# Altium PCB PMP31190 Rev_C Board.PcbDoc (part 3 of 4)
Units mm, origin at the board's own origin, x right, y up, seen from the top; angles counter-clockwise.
Board outline 175.26 x 91.44 mm, 4 copper layers (Top Layer, Mid-Layer 1, Mid-Layer 2, Bottom Layer), stack 1.473 mm thick; 252 components, 140 nets, 735 pads, 501 vias.
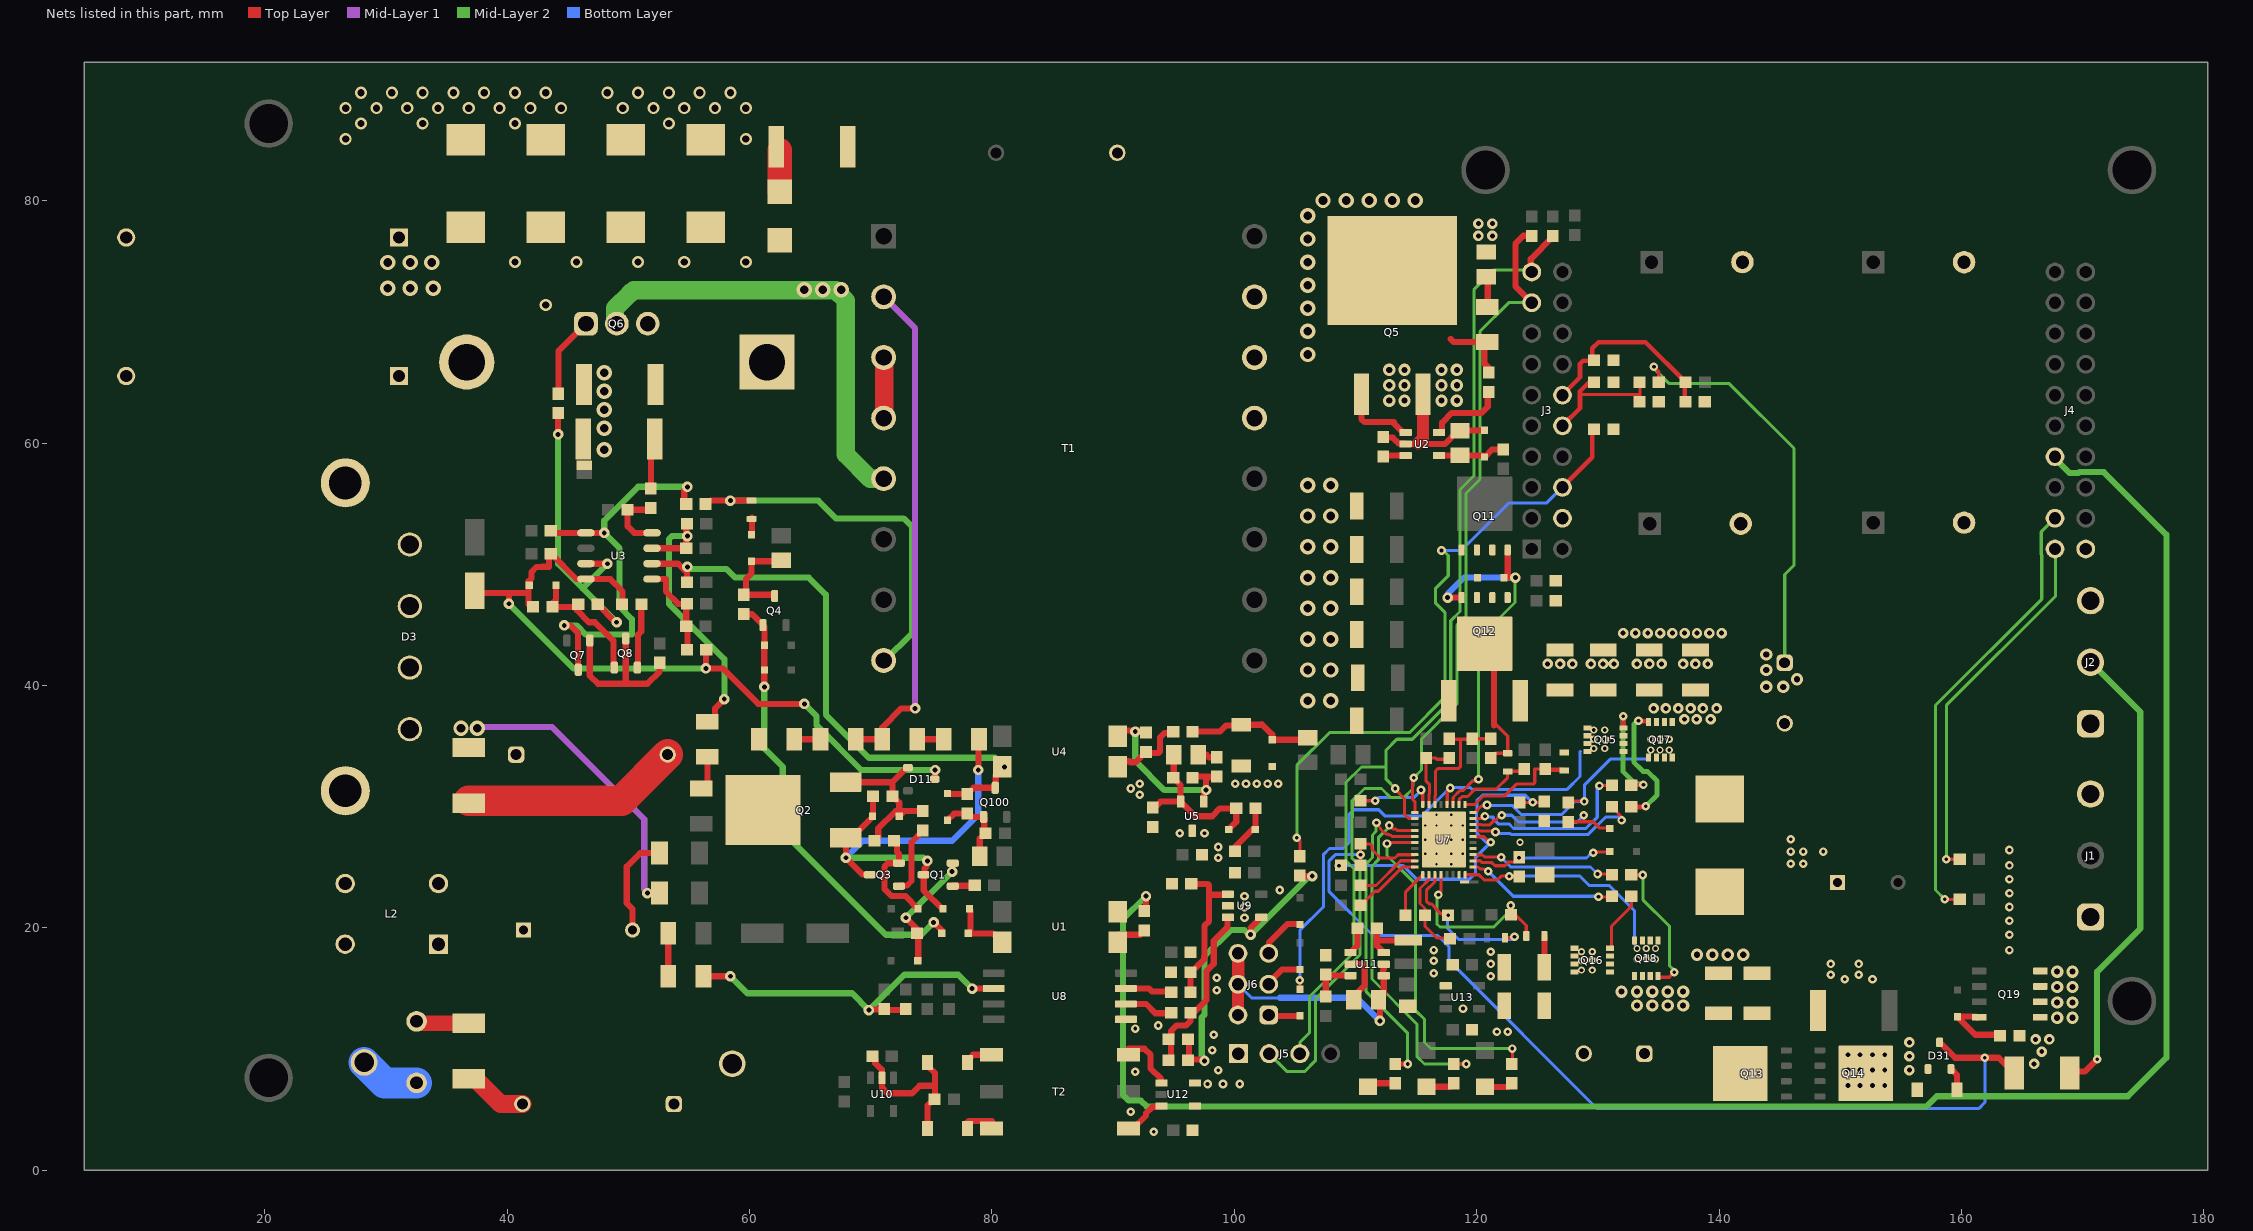
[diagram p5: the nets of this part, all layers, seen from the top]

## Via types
v1: diameter 0.711, hole 0.305, Top Layer to Bottom Layer, 109 vias
v2: diameter 0.864, hole 0.406, Top Layer to Bottom Layer, 105 vias
v3: diameter 1.27, hole 0.711, Top Layer to Bottom Layer, 72 vias
v4: diameter 0.864, hole 0.406, Top Layer to Bottom Layer, tented both sides, 40 vias
v5: diameter 1.016, hole 0.508, Top Layer to Bottom Layer, 38 vias
v6: diameter 1, hole 0.6, Top Layer to Bottom Layer, 26 vias
v7: diameter 0.6, hole 0.3, Top Layer to Bottom Layer, tented top, 24 vias
v8: diameter 0.711, hole 0.305, Top Layer to Bottom Layer, tented both sides, 22 vias
v9: diameter 0.711, hole 0.305, Top Layer to Bottom Layer, tented top, 21 vias
v10: diameter 0.5, hole 0.2, Top Layer to Bottom Layer, 16 vias
v11: diameter 0.864, hole 0.406, Top Layer to Bottom Layer, tented top, 12 vias
v12: diameter 1, hole 0.6, Top Layer to Bottom Layer, tented top, 9 vias
v13: diameter 1, hole 0.6, Top Layer to Bottom Layer, tented both sides, 5 vias
v14: diameter 0.6, hole 0.3, Top Layer to Bottom Layer, 1 vias
v15: diameter 0.711, hole 0.305, Top Layer to Bottom Layer, tented bottom, 1 vias

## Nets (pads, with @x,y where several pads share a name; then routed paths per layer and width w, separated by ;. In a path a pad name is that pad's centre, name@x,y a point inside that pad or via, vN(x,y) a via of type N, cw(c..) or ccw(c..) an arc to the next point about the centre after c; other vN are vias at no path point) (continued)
FB: C26.1 D101.1 Q100.3 R100.2 U3.2 U4.4 | length 49.2
  Top Layer w0.508: U3.2@51.949,50.049 51.96,50.038 54.102,50.038 v2@54.61,49.53 ; C26.1@54.826,48.514 54.826,49.746 v2(54.864,49.784) ; D101.1@76.327,31.072 76.35,31.049 77.955,31.049 R100.2@77.978,31.026 77.978,31.051 78.48,31.553 Q100.3@80.264,31.553 80.31,31.599 80.31,32.621 80.963,33.274 v2(81.026,33.274)
  Mid-Layer 2 w0.508: v2(54.864,49.784) 55.042,49.606 58.09,49.606 58.801,48.895 64.897,48.895 66.294,47.498 66.294,37.592 69.85,34.036 80.264,34.036 v2(81.026,33.274)
NetC2_1: C2.1 C3.1 D3.1 D4.2 R2.2 R3.2 T1.2 | length 41.7
  Top Layer w0.508: R2.2@68.76,35.56 68.76,35.613 68.834,35.687 68.961,35.56 R3.2@70.94,35.56 70.94,36.523 72.517,38.1 v2(73.66,38.1)
  Mid-Layer 1 w0.508: T1.2@71.06,72.06 73.66,69.46 v2(73.66,38.1)
  other v3: 30.149,72.771 31.999,72.771 33.909,72.771 30.149,74.896 31.999,74.896 33.763,74.896
NetC4_1: C4.1 L2.1 TP1.1
NetC4_2: C4.2 R7.2 | length 5.3
  Top Layer w1.5: R7.2@36.83,7.53 37.38,7.53 39.449,5.461 C4.2@41.248,5.461
NetC5_1: C5.1 L1.1 L2.2
NetC5_2: C5.2 R8.2 | length 18.2
  Top Layer w0.508: R8.2@36.83,30.28 R8.2@36.83,30.48
  Top Layer w2.54: R8.2@36.83,30.48 49.43,30.48 C5.2@53.24,34.29
NetC6_2: C6.2 D11.1 D100.2 Q2.3 R9.2 R11.2 | length 14.7
  Top Layer w0.508: Q2.3@67.916,31.998 67.922,32.004 71.764,32.004 ; R11.2@70.32,27.178 70.345,27.178 70.566,27.399 70.566,27.424 70.612,27.47 70.612,28.194 72.047,29.629 72.347,29.629 ; D11.1@73.068,33.208 72.968,33.208 71.764,32.004 ; R9.2@74.295,29.629 72.766,29.629 ; 71.764,32.004 71.793,31.975 C6.2@71.793,30.861 71.818,30.861 72.347,30.332 72.347,29.629 ; 72.347,29.629 D100.2@72.347,29.21 72.766,29.629 ; 72.347,29.629 72.766,29.629
NetC12_1: C12.1 D12.1 Q4.3 R14.2 | length 8.1
  Top Layer w0.508: Q4.3@62.06,47.378 61.96,47.478 R14.2@59.52,47.478 59.69,47.648 59.69,48.768 60.165,49.243 D12.1@60.165,50.24 62.432,50.24 62.516,50.324 C12.1@62.605,50.324
NetC14_1: C14.1 R17.1 | length 2.6
  Top Layer w0.508: C14.1@120.771,73.727 120.904,73.594 120.904,71.273 R17.1@120.86,71.228
NetC15_1: C15.1 U2.3 | length 1.8
  Top Layer w0.508: C15.1@112.395,58.89 112.472,58.967 U2.3@114.198,58.953
NetC16_1: C16.1 D102.1 R16.1 U2.4 | length 5.8
  Top Layer w0.508: U2.4@116.904,58.953 U2.4@116.89,58.967 116.895,58.973 C16.1@118.536,58.973 ; C16.1@118.516,58.953 C16.1@118.536,58.973 ; C16.1@118.643,59.03 118.618,59.055 C16.1@118.536,58.973 ; R16.1@122.174,59.474 121.28,59.474 D102.1@120.65,58.844 120.515,58.979 C16.1@118.618,58.979 118.612,58.973 C16.1@118.536,58.973
NetC17_1: C17.1 R19.1 R25.2 U3.3 | length 23.4
  Top Layer w0.5: R19.1@57.15,37.01 57.15,38.1 v2(57.912,38.862)
  Top Layer w0.508: U3.3@51.949,51.319 54.764,51.319 C17.1@54.774,51.309 R25.2@54.774,52.969
  Mid-Layer 2 w0.5: v2(54.864,52.324) 53.594,52.324 53.34,52.07 53.34,46.736 57.912,42.164 v2(57.912,38.862)
NetC18_1: C18.1 R18.1 R26.2 U3.1 | length 8.2
  Top Layer w0.5: U3.1@51.949,48.779 51.96,48.768 53.086,48.768 53.086,47.752 54.102,46.736 R26.2@54.774,46.736 ; R18.1@54.826,42.926 54.864,42.964 54.864,44.774 C18.1@54.774,44.864 R26.2@54.774,46.736 ; R26.2@54.826,46.736 R26.2@54.774,46.736
NetC19_1: C19.1 D15.1 R24.1 R29.2 | length 10.8
  Top Layer w0.508: R29.2@96.558,36.195 98.806,36.195 99.314,36.703 100.535,36.703 C19.1@100.584,36.752 102.157,36.752 102.235,36.83 103.124,35.941 D15.1@103.124,35.517 105.748,35.517 106.045,35.814 R24.1@106.045,35.687
NetC20_1: C20.1 Q7.3 R21.1 U3.5 | length 34.8
  Top Layer w0.508: C20.1@43.589,52.779 43.779,52.589 U3.5@46.499,52.589 46.51,52.578 v2(48.006,52.578) ; v2(44.704,44.958) 45.212,44.958 45.829,44.341 45.829,41.293 Q7.3@45.867,41.293 ; R21.1@54.774,54.969 54.774,55.208 54.61,55.372 54.61,56.134 v2(54.864,56.388)
  Mid-Layer 2 w0.508: v2(44.704,44.958) 45.72,44.958 46.482,44.196 50.292,44.196 50.292,45.466 49.276,46.482 49.276,51.308 v2(48.006,52.578) 48.006,53.594 50.8,56.388 v2(54.864,56.388)
NetC21_1: C21.1 R23.1 U3.4 | length 5.6
  Top Layer w0.508: R23.1@51.853,54.644 51.703,54.494 C21.1@49.914,54.494 49.933,54.476 49.933,53.134 50.478,52.589 U3.4@51.949,52.589
NetC23_1: C23.1 D16.2 Q8.1 R30.2 | length 10.9
  Top Layer w0.508: D16.2@44.026,48.26 44.026,47.074 43.688,46.736 43.726,46.698 R30.2@43.726,46.482 C23.1@45.669,46.482 ; C23.1@45.72,46.68 C23.1@45.72,46.736 ; C23.1@45.867,46.68 45.72,46.533 45.72,46.228 46.736,45.212 47.244,45.212 48.768,43.688 48.768,41.402 48.834,41.468 Q8.1@48.834,41.472
NetC23_2: C23.2 R22.1 U3.7 | length 26.1
  Top Layer w0.508: v2(44.196,60.706) 44.196,62.444 R22.1@44.223,62.471 ; U3.7@46.499,50.049 46.493,50.049 46.482,50.038 v2(48.26,50.038) ; C23.2@47.467,46.68 48.935,45.212 v2(49.022,45.212)
  Mid-Layer 2 w0.508: v2(44.196,60.706) 44.196,50.038 46.228,48.006 ; v2(48.26,50.038) 46.228,48.006 ; v2(49.022,45.212) 46.228,48.006
NetC24_1: C24.1 R31.2 R34.1 U4.2 U5.1 | length 15.9
  Top Layer w0.508: U4.2@90.562,36.282 92.534,36.282 R31.2@92.71,36.106 ; C24.1@96.393,32.385 96.482,32.474 97.917,32.474 ; U5.1@97.47,30.41 97.485,30.425 97.485,31.095 97.663,31.273 v2(97.663,31.369) 97.663,32.22 97.917,32.474 ; R34.1@98.552,32.474 97.917,32.474
  Mid-Layer 2 w0.508: v11(91.821,36.195) 91.821,33.782 94.234,31.369 v2(97.663,31.369)
NetC24_2: C24.2 C25.1 D17.2 R32.1 R37.2 U5.2 | length 14
  Top Layer w0.508: R37.2@93.265,29.924 93.424,29.924 93.91,30.41 U5.2@95.57,30.41 ; C25.1@94.996,34.279 94.996,32.423 C24.2@94.958,32.385 94.983,32.385 95.204,32.164 95.204,32.139 95.55,31.793 95.55,30.43 U5.2@95.57,30.41 ; D17.2@99.532,28.12 100.154,28.743 R32.1@100.154,29.858 100.141,29.845 98.806,29.845 98.171,29.21 96.77,29.21 U5.2@95.57,30.41
NetC25_2: C25.2 R34.2 | length 1.9
  Top Layer w0.508: C25.2@96.785,34.29 C25.2@97.028,34.29 97.701,34.29 97.917,34.074 R34.2@98.552,34.074
NetC34_2: C34.2 R47.1 U7.30 | length 7.3
  Top Layer w0.254: U7.30@118.547,30.18 118.547,30.536 118.567,30.556 118.567,30.598 118.804,30.835 119.253,30.835 119.881,31.463 121.633,31.463 122.555,32.385 R47.1@122.555,32.905 R47.1@122.405,32.905
  Top Layer w0.3: R47.1@122.555,32.905 123.724,32.905 C34.2@123.914,33.095
NetC35_1: C35.1 R48.1 U7.29 | length 10
  Top Layer w0.254: U7.29@119.047,30.18 119.836,30.18 120.186,30.53 120.192,30.53 120.523,30.861 122.276,30.861 123.266,31.852 124.714,31.852 124.714,31.902 124.79,31.979 124.79,33.068 124.763,33.095 125.35,33.095 C35.1@125.451,32.995
  Top Layer w0.35: C35.1@125.652,33.095 125.713,33.034 127.155,33.034 R48.1@127.216,32.973
NetC40_1: C40.1 C41.1 C42.1 C43.1 C44.1 Q13.5 Q13.6 Q13.7 Q13.8 Q13.9@141.743,7.975 Q16.5 Q16.6 Q16.7 Q16.8 Q16.9 R53.1 R55.2 | length 2.6
  Top Layer w0.508: C40.1@125.575,16.747 125.603,16.775 125.603,19.304 125.588,19.319 R53.1@125.588,19.322
  other v7: 128.651,16.51 129.54,16.51 128.651,17.272 129.54,17.272 128.651,18.034 129.54,18.034
NetC45_1: C45.1 L3.2 Q16.1 Q16.2 Q16.3 Q18.5 Q18.6 Q18.7 Q18.8 Q18.9 U7.18 | length 19
  Top Layer w0.254: U7.18@119.047,24.38 120.17,24.38 120.597,23.952 121.72,23.952 122.024,24.257 v9(122.682,24.257)
  Top Layer w0.35: v9(122.682,24.257) C45.1@123.457,24.257
  Bottom Layer w0.254: v9(122.682,24.257) 128.524,24.257 129.286,23.495 130.937,23.495 133.022,21.41 133.022,18.622
  other v7: 133.223,17.399 133.985,17.399 134.747,17.399 133.223,18.288 133.985,18.288 134.747,18.288
NetC45_2: C45.2 D19.1 U7.20 | length 12
  Top Layer w0.254: U7.20@119.697,25.53 120.283,25.53 120.438,25.375 121.25,25.375 121.504,25.121 122.316,25.121 122.642,25.446 123.147,25.446 C45.2@123.488,25.787 ; v1(129.616,26.187) 129.667,26.238 130.929,26.238 D19.1@130.98,26.289
  Bottom Layer w0.254: v1(123.495,25.781) 123.52,25.756 129.061,25.756 129.492,26.187 v1(129.616,26.187)
NetC46_1: C46.1 L3.1 Q15.1 Q15.2 Q15.3 Q17.5 Q17.6 Q17.7 Q17.8 Q17.9 U7.28 | length 19.4
  Top Layer w0.254: U7.28@119.697,29.53 119.868,29.53 120.386,30.047 120.756,30.047 v1(120.844,30.135) ; C46.1@127.541,30.339 127.57,30.339 127.686,30.455 128.854,30.455 v1(128.88,30.429)
  Bottom Layer w0.254: v1(120.844,30.135) 120.813,30.135 120.777,30.099 122.936,30.099 123.698,29.337 127,29.337 128.092,30.429 v1(128.88,30.429) 128.88,30.582 128.905,30.607 128.905,31.801 131.025,33.921 134.273,33.921
  other v7: 134.366,34.671 135.128,34.671 135.89,34.671 134.366,35.56 135.128,35.56 135.89,35.56
NetC46_2: C46.2 D18.1 U7.26 | length 13.7
  Top Layer w0.254: U7.26@119.697,28.53 119.699,28.528 120.352,28.528 120.381,28.499 121.067,28.499 121.407,28.84 121.502,28.84 121.949,29.286 v1(122.072,29.286) ; C46.2@127.541,28.739 127.57,28.739 127.584,28.753 128.854,28.753 ; 128.854,28.88 128.854,28.753 ; D18.1@130.98,28.194 130.955,28.219 130.15,28.219 129.616,28.753 128.854,28.753
  Bottom Layer w0.254: v1(122.072,29.286) 122.885,29.286 123.444,28.727 128.27,28.727 v1(128.829,29.286)
NetC48_2: C48.2 R53.2 U7.14 | length 14.7
  Top Layer w0.254: v1(116.84,22.733) 117.047,22.94 U7.14@117.047,24.38 ; v8(122.809,21.844) v8@122.822,21.831 ; C48.2@122.822,21.057 123.165,21.057 123.19,21.082 124.088,20.184 R53.2@124.088,19.322 R53.2@124.088,19.313
  Top Layer w0.354: C48.2@122.822,21.057 v8@122.822,21.831
  Mid-Layer 2 w0.254: v1(116.84,22.733) 116.713,22.606 116.713,20.32 116.967,20.066 121.412,20.066 122.809,21.463 v8(122.809,21.844)
NetC49_1: C49.1 R57.2 U7.13 | length 12.6
  Top Layer w0.254: U7.13@116.547,24.38 116.547,23.837 116.53,23.82 116.53,23.772 115.848,23.09 115.848,22.201 116.078,21.971 116.273,21.971 116.591,21.653 116.591,21.611 117.043,21.158 117.513,21.158 v1(117.64,21.031) ; R57.2@122.34,19.177 123.038,19.177 v1(123.114,19.253)
  Bottom Layer w0.254: v1(117.64,21.031) 117.64,20.993 117.602,20.955 117.602,19.939 118.491,19.05 122.911,19.05 v1(123.114,19.253)
NetC51_1: C51.1 R71.1 R73.2 U9.3 | length 14.6
  Top Layer w0.508: R71.1@94.582,9.066 94.582,9.111 94.783,9.312 94.783,10.965 94.791,10.973 94.8,10.973 94.8,11.488 95.25,11.938 95.663,11.938 95.673,11.948 96.022,11.948 96.393,12.319 96.391,12.321 96.391,12.956 96.393,12.954 R73.2@96.52,13.081 ; R73.2@96.391,12.991 96.481,13.081 R73.2@96.52,13.081 ; U9.3@99.469,20.865 99.441,20.837 99.441,20.066 98.298,18.923 98.298,17.018 97.688,16.408 97.688,14.039 96.73,13.081 R73.2@96.52,13.081
NetC53_2: C53.2 R72.1 R75.2 U8.2 | length 29.8
  Top Layer w0.508: R72.1@56.261,16.002 v2(58.42,16.002) ; v2(69.85,13.208) 69.895,13.253 71.075,13.253 71.12,13.208 C53.2@72.898,13.208 ; v2(78.359,14.986) U8.2@80.148,14.986
  Mid-Layer 2 w0.508: v2(58.42,16.002) 59.817,14.605 68.453,14.605 v2(69.85,13.208) 72.771,16.129 77.216,16.129 v2(78.359,14.986)
NetC58_1: C58.1 R74.2 R76.2 U9.1 | length 12.6
  Top Layer w0.508: R74.2@96.391,14.676 96.391,16.312 C58.1@96.383,16.32 96.408,16.32 97.011,16.922 97.04,16.922 97.536,17.418 97.536,20.174 97.917,20.555 97.917,22.733 ; R76.2@96.44,23.615 97.797,23.615 97.917,23.495 97.917,22.733 ; U9.1@99.469,22.765 99.469,22.761 99.441,22.733 97.917,22.733
NetC59_1: C59.1 U11.1 | length 2.2
  Top Layer w0.508: U11.1@109.581,17.953 110.156,18.528 C59.1@110.156,19.948
NetC59_2: C59.2 L4.1 U11.6 | length 4.9
  Top Layer w0.508: C59.2@111.756,19.948 111.756,18.974 ; U11.6@112.331,17.953 112.331,17.971 111.756,18.546 111.756,18.974 ; L4.1@114.351,18.984 114.208,18.984 114.173,18.948 111.781,18.948 111.756,18.974
NetC61_2: C61.2 C67.2 D23.1 D24.1 U10.2 | length 13
  Top Layer w0.508: C61.2@70.129,9.392 70.154,9.392 70.375,9.171 70.375,8.822 70.917,8.28 U10.2@70.917,7.634 ; U10.2@70.883,7.668 U10.2@70.917,7.634 ; U10.2@70.929,7.622 U10.2@70.917,7.634 ; U10.2@70.931,7.62 70.931,6.793 71.374,6.35 73.406,6.35 74.028,6.972 75.3,6.972 ; D23.1@74.676,8.636 75.3,8.012 75.3,6.972 ; D24.1@74.687,3.922 74.687,5.345 75.3,5.958 75.3,6.972
NetC62_1: C62.1 J6.2 J6.4 J6.6 U11.4 U11.5 | length 23.4
  Top Layer w0.508: J6.6@100.297,17.887 100.297,18.001 J6.6@100.33,18.034 ; v2(112.014,12.319) 112.014,13.97 111.929,14.055 C62.1@111.897,14.055 112.331,14.489 U11.4@112.331,16.053 112.268,16.116 112.268,16.51 112.331,16.573 U11.5@112.331,17.003
  Top Layer w1.016: J6.2@100.297,12.807 J6.4@100.297,15.347 100.33,15.379 J6.6@100.33,18.034
  Bottom Layer w0.254: J6.4@100.297,15.347 101.42,14.224 102.325,14.224 102.359,14.191 103.316,14.191 103.35,14.224 103.759,14.224
  Bottom Layer w0.508: 103.759,14.224 110.109,14.224 v2(112.014,12.319)
NetC70_1: C70.1 J3.23 R79.2 | length 53.6
  Top Layer w0.254: v1(105.156,27.432) 105.41,27.178 R79.2@105.41,25.9
  Top Layer w0.381: J3.23@127.07,56.347 129.54,58.817 129.54,61.214 129.601,61.153 C70.1@129.673,61.153
  Mid-Layer 2 w0.254: v1(105.156,27.432) 105.156,33.401 107.874,36.119 114.478,36.119 117.373,39.014 117.373,46.025 116.586,46.812 116.586,47.981 117.653,49.047 117.653,50.724 117.272,51.105 117.094,51.105 v1(117.094,51.13)
  Bottom Layer w0.254: v1(117.094,51.13) 118.72,51.13 122.657,55.067 125.79,55.067 J3.23@127.07,56.347
NetC72_1: C72.1 J3.25 R84.1 R86.1 | length 11.5
  Top Layer w0.254: 128.524,64.008 133.477,64.008 ; R86.1@133.422,63.411 133.477,63.466 133.477,64.008 ; R84.1@133.422,65.024 133.477,64.969 133.477,64.008
  Top Layer w0.381: J3.25@127.07,61.427 128.524,62.881 128.524,64.008 128.524,64.262 129.286,65.024 C72.1@129.686,65.024
NetC73_1: C73.1 J3.26 R85.1 R87.1 | length 16.8
  Top Layer w0.381: J3.26@127.07,63.967 128.524,65.421 128.524,66.548 128.778,66.802 129.54,66.802 129.578,66.84 C73.1@129.673,66.84 129.54,66.973 129.54,67.818 130.048,68.326 133.93,68.326 R85.1@137.232,65.024 137.16,64.952 137.16,63.246 137.212,63.298 R87.1@137.212,63.411
NetC100_1: C100.1 D101.2 Q100.1 R100.1 R101.1 | length 6.9
  Top Layer w0.508: D101.2@76.327,28.872 76.881,29.426 R100.1@77.978,29.426 77.978,29.401 78.199,29.18 78.224,29.18 78.251,29.153 Q100.1@79.314,29.153 79.36,29.107 79.36,27.917 R101.1@79.464,27.813 79.439,27.813 78.994,27.368 C100.1@78.994,25.908
NetD1_1: D1.1 D2.1 U1.4 | length 5.3
  Top Layer w0.508: D1.1@78.15,21.577 78.15,21.545 78.232,21.463 78.232,19.722 D2.1@78.05,19.54 80.091,19.54 80.199,19.432 80.327,19.432 80.835,18.924 U1.4@80.835,18.796
NetD3_2: D3.2 D10.2 L1.2 | length 8.6
  Top Layer w0.508: L1.2@50.347,19.812 50.347,21.545 49.86,22.032 49.86,25.052 50.971,26.162 D10.2@52.579,26.162
NetD3_3: D3.3 D9.2 L2.3 R8.1 | length 24.9
  Top Layer w0.508: v11(51.562,22.86) D9.2@52.579,22.86 ; D9.2@52.324,22.352 D9.2@52.832,22.86
  Mid-Layer 1 w0.508: v3(37.53,36.46) 37.646,36.576 43.688,36.576 51.308,28.956 51.308,23.21 51.562,22.956 v11(51.562,22.86)
  other v3: 36.183,36.46
NetD4_1: D4.1 D5.2
  other v6: 26.67,85.09 27.94,86.36 26.67,87.63 29.21,87.63 31.75,87.63 27.94,88.9 30.48,88.9 33.02,88.9 35.56,88.9 38.1,88.9 40.64,88.9 43.18,88.9
  other v12: 33.02,86.36 40.64,86.36 34.29,87.63 36.83,87.63 39.37,87.63 41.91,87.63 44.45,87.63
NetD5_1: D5.1 D103.2
  other v6: 40.64,74.93 45.72,74.93 50.8,74.93
  other v12: 43.18,71.39
NetD6_1: D6.1 D104.1
  other v13: 54.61,74.93 59.69,74.93
NetD6_2: D6.2 R12.2 | length 3.8
  Top Layer w1.2: R12.2@62.201,84.455 R12.2@62.484,84.172
  Top Layer w2: D6.2@62.484,80.74 R12.2@62.484,84.172
NetD7_1: D7.1 Q3.2 R11.1 | length 8.9
  Top Layer w0.508: R11.1@71.92,27.178 71.945,27.178 72.166,26.957 72.166,26.259 72.32,26.105 Q3.2@72.32,25.334 72.31,25.324 71.418,25.324 71.12,25.026 71.12,23.203 71.697,22.626 72.841,22.626 D7.1@73.89,21.577 D7.1@73.914,21.601 ; Q3.2@72.374,25.334 Q3.2@72.574,25.334
NetD8_1: D8.1 Q1.2 R10.2 | length 10.3
  Top Layer w0.508: v2(72.898,20.828) 73.914,19.812 R10.2@73.914,19.469 ; R10.2@73.825,19.558 R10.2@73.914,19.469 ; D8.1@73.871,17.272 73.914,17.272 R10.2@73.914,19.469 ; v11(76.708,24.638) 76.737,24.667 76.737,25.305 Q1.2@76.765,25.334
  Mid-Layer 2 w0.508: v2(72.898,20.828) v11(76.708,24.638)
NetD12_2: D12.2 R13.1 | length 1.4
  Top Layer w0.508: D12.2@60.165,52.44 60.198,52.473 R13.1@60.198,53.848
NetD17_1: D17.1 R32.2 R33.2 | length 4.5
  Top Layer w0.508: R33.2@100.044,26.31 99.97,26.31 99.949,26.289 99.949,26.543 101.526,28.12 D17.1@101.732,28.12 101.732,29.835 R32.2@101.754,29.858
NetD20_1: D20.1 R62.1 | length 2.4
  Top Layer w0.508: D20.1@111.04,6.883 111.332,7.175 R62.1@113.274,7.175
NetD21_1: D21.1 R63.1 | length 2.4
  Top Layer w0.508: D21.1@115.866,6.883 117.806,6.883 R63.1@118.098,7.175
NetD22_1: D22.1 R64.1 | length 2.4
  Top Layer w0.508: D22.1@120.695,6.883 120.879,6.883 120.904,6.858 122.59,6.858 R64.1@122.907,7.175
NetD23_2: D23.2 T2.4 | length 2.3
  Top Layer w0.508: D23.2@77.964,8.89 77.964,9.043 78.449,9.527 T2.4@79.943,9.527
NetD24_2: D24.2 T2.6 | length 2.3
  Top Layer w0.508: D24.2@77.962,3.922 78.104,4.064 80.01,4.064 79.945,3.999 T2.6@79.945,3.922
NetD25_1: D25.1 Q11.4 Q12.4 U7.31 | length 32.1
  Top Layer w0.254: U7.31@118.047,30.18 118.047,30.671 118.065,30.689 118.065,30.736 118.084,30.755 118.084,30.797 118.604,31.318 118.872,31.318 119.685,32.131 120.015,32.131 v1(120.142,32.258)
  Top Layer w0.508: v2(117.602,47.244) 118.237,47.244 118.238,47.245 Q12.4@118.745,47.245 ; Q11.4@122.555,51.18 122.555,49.192 D25.1@122.258,48.895 v2(123.19,48.895)
  Mid-Layer 2 w0.254: v1(120.142,32.258) 120.142,43.815 123.165,46.838 123.165,48.87 v2(123.19,48.895)
  Bottom Layer w0.508: v2(117.602,47.244) 117.602,47.549 118.948,48.895 v2(123.19,48.895)
NetD25_2: D25.2 Q11.1 Q11.2 Q11.3 Q12.1 Q12.2 Q12.3
NetD26_1: D26.1 J6.1 | length 2.7
  Top Layer w0.508: J6.1@102.837,12.807 102.837,12.733 102.87,12.7 102.902,12.732 D26.1@105.41,12.732
NetD27_1: D27.1 J6.3 | length 3.1
  Top Layer w0.508: J6.3@102.837,15.347 102.837,15.461 103.942,16.566 D27.1@105.41,16.566
NetD28_1: D28.1 J6.5 | length 4.3
  Top Layer w0.508: J6.5@102.837,17.887 102.837,17.813 102.87,17.78 102.87,18.796 104.394,20.32 105.367,20.32 D28.1@105.41,20.277
NetD29_2: D29.2 Q19.4 R94.2 | length 6.1
  Top Layer w0.254: R94.2@163.182,11.1 163.182,11.163 R94.2@163.195,11.176
  Top Layer w0.508: Q19.4@161.455,12.624 161.341,12.624 161.29,12.573 161.196,12.667 D29.2@159.664,12.667 161.155,11.176 R94.2@163.195,11.176
NetD30_1: D30.1 D31.2 | length 1.9
  Top Layer w0.508: D31.2@159.141,8.349 159.639,7.851 159.639,6.731 159.625,6.717 D30.1@159.625,6.629
NetD31_3: D31.3 R68.2 R69.1 R93.1 U7.8 | length 85.7
  Top Layer w0.254: R69.1@110.401,25.146 v1@110.401,26.035 ; v1(110.414,26.035) 110.414,26.911 R68.2@110.401,26.924 111.205,26.924 111.354,26.775 111.354,26.455 112.053,25.756 113.253,25.756 113.527,26.03 U7.8@114.897,26.03 ; R93.1@164.338,8.001 164.349,8.012 R93.1@164.349,8.026
  Top Layer w0.508: D31.3@158.191,10.549 159.469,9.271 v1(161.925,9.271) 163.068,9.271 R93.1@164.338,8.001
  Bottom Layer w0.254: v1(110.414,26.035) 108.331,26.035 107.823,25.527 107.823,22.987 111.442,19.367 116.776,19.367 117.729,18.415 117.729,17.272 129.921,5.08 161.417,5.08 161.925,5.588 v1(161.925,9.271)
NetD103_1: D103.1 D104.2
  other v6: 53.34,86.36 49.53,87.63 52.07,87.63 54.61,87.63 57.15,87.63 59.69,87.63 48.26,88.9 50.8,88.9 53.34,88.9 55.88,88.9 58.42,88.9
  other v12: 59.69,85.09
NetF1_1: F1.1 L2.4 R7.1 | length 4.5
  Top Layer w1.27: F1.1@32.52,12.283 32.673,12.13 R7.1@36.83,12.13
  Bottom Layer w1.27: F1.1@32.52,12.283 F1.1@32.596,12.206
NetF1_2: F1.2 TP2.1 | length 5
  Bottom Layer w2.54: TP2.1@28.194,8.89 29.881,7.203 F1.2@32.52,7.203
NetJ2_1: J2.1 Q19.5 Q19.6 Q19.7 Q19.8
  other v5: 167.894,12.573 169.164,12.573 167.894,13.843 169.164,13.843 167.894,15.113 169.164,15.113 167.894,16.383 169.164,16.383
NetJ2_2: J2.2 R93.2 | length 38.8
  Top Layer w0.254: R93.2@168.91,8.128 168.949,8.089 R93.2@168.949,8.026
  Top Layer w0.508: R93.2@168.91,8.128 170.18,8.128 v1(171.196,9.144)
  Mid-Layer 2 w0.508: J2.2@170.65,41.91 174.752,37.808 174.752,19.939 171.196,16.383 v1(171.196,9.144)
NetJ4_39: J4.39 R88.1 | length 37.3
  Top Layer w0.254: v1@158.517,22.458 v1(158.623,22.352) R88.1@159.855,22.352
  Mid-Layer 2 w0.254: v1(158.623,22.352) 157.861,23.114 157.861,38.354 166.624,47.117 166.624,50.754 166.579,50.798 166.579,52.676 J4.39@167.71,53.807
NetJ4_40: J4.40 R89.1 | length 30.5
  Top Layer w0.254: v1(158.75,25.654) R89.1@159.855,25.654
  Mid-Layer 2 w0.254: v1(158.75,25.654) 158.75,38.354 167.767,47.371 167.767,51.21 J4.40@167.71,51.267
NetQ1_1: Q1.1 R6.2 | length 1.8
  Top Layer w0.508: Q1.1@76.765,23.434 76.796,23.464 78.545,23.464 R6.2@78.575,23.495
NetQ2_2: Q2.2 R4.1
NetQ3_1: Q3.1 R9.1 | length 5.8
  Top Layer w0.5: Q3.1@72.32,23.434 72.37,23.484 72.986,23.484 73.361,23.859 73.361,27.07 74.295,28.004 R9.1@74.295,28.029
NetQ5_1: Q5.1 U2.1 | length 6.2
  Top Layer w0.508: Q5.1@110.49,64.028 110.49,61.976 110.744,61.722 113.157,61.722 113.157,61.65 113.94,60.867 U2.1@114.14,60.867
NetQ5_4: Q5.4 R17.2 R90.1 T1.13 T1.14 T1.15 | length 5.8
  Top Layer w0.508: 117.856,68.58 118.108,68.328 R17.2@120.86,68.328 120.65,68.119 120.65,66.548 120.999,66.199 R90.1@120.999,65.824
  other v3: 106.045,67.31 106.045,69.215 106.045,71.12 106.045,73.025 106.045,74.93 106.045,76.835 106.045,78.74 107.315,80.01 109.22,80.01 111.125,80.01 113.03,80.01 114.935,80.01
NetQ6_1: Q6.1 R22.2 | length 6.7
  Top Layer w0.508: R22.2@44.223,64.071 44.223,67.576 Q6.1@46.496,69.85
NetQ6_2: Q6.2 R12.1 T1.5 | length 38.1
  Mid-Layer 2 w1.524: Q6.2@49.046,69.85 48.895,69.85 48.895,71.12 50.165,72.39 50.243,72.39 50.456,72.603 67.097,72.603 67.945,71.755 67.945,59.055 69.94,57.06 T1.5@71.06,57.06
  other v3: 64.516,72.644 66.04,72.644 67.564,72.644
NetQ6_3: Q6.3 R23.2 R27.2 R28.2 | length 3.8
  Top Layer w0.508: R23.2@51.853,56.244 R28.2@51.853,60.004
NetQ7_1: Q7.1 Q8.3 R36.2 | length 13.8
  Top Layer w0.508: Q7.1@46.817,43.693 46.817,40.813 47.498,40.132 49.784,40.132 ; Q8.3@49.784,43.872 49.784,40.132 ; R36.2@52.578,41.872 52.578,41.148 51.562,40.132 49.784,40.132
NetQ8_2: Q8.2 R35.2 | length 5.5
  Top Layer w0.508: Q8.2@50.734,41.472 50.734,41.468 50.8,41.402 50.8,44.196 51.054,44.45 51.054,46.655 R35.2@51.079,46.68
NetQ12_5: Q12.5 Q12.6 Q12.7 Q12.8 Q12.9@120.65,43.445 R46.1 R47.2 R102.2 | length 11.7
  Top Layer w0.3: R102.2@121.158,33.998 121.158,34.023 121.483,34.348 121.508,34.348 121.577,34.417 122.543,34.417 R47.2@122.555,34.405 122.555,35.815 121.413,36.958
  Top Layer w0.508: Q12.9@120.65,43.445 121.425,42.67 121.423,41.655 121.413,36.958 121.412,36.703
NetQ15_4: Q15.4 R49.2 | length 8.7
  Top Layer w0.254: R49.2@132.753,31.75 132.766,31.75 132.817,31.801 v1(133.756,31.801)
  Top Layer w0.4: v1(132.08,37.465) 132.089,37.456 132.089,36.503 Q15.4@132.099,36.494
  Mid-Layer 2 w0.4: v1(132.08,37.465) 132.08,32.893 132.97,32.003 133.113,31.86 133.697,31.86 v1(133.756,31.801)
NetQ16_4: Q16.4 R50.1 | length 5
  Top Layer w0.254: Q16.4@131.079,18.316 131.087,18.316 131.115,18.288 131.115,20.117 132.753,21.755 R50.1@132.753,22.606
NetQ17_4: Q17.4 R51.1 | length 10.8
  Top Layer w0.254: v1@133.909,29.972 v1(133.96,30.023)
  Top Layer w0.4: R51.1@132.753,29.972 v1@133.909,29.972 ; v1(133.35,37.084) 133.395,37.039 134.177,37.039 134.187,37.029 Q17.4@134.187,36.993 Q17.4@134.184,36.996
  Mid-Layer 2 w0.254: v1(133.96,30.023) v1@133.96,30.048
  Mid-Layer 2 w0.4: v1(133.35,37.084) 133.266,37.084 133.012,36.83 132.969,36.83 132.969,33.655 133.605,33.019 133.731,32.893 134.112,32.893 134.874,32.131 134.874,30.937 v1(133.96,30.023)
NetQ18_4: Q18.4 R52.1 | length 11.6
  Top Layer w0.254: R52.1@132.753,24.384 132.766,24.384 132.817,24.333 133.68,24.333 v1(133.706,24.359) ; Q18.4@134.972,15.922 135.886,15.922 v1(136.296,16.332)
  Mid-Layer 2 w0.254: v1(133.706,24.359) 133.706,22.327 135.89,20.142 135.89,16.891 136.296,16.485 v1(136.296,16.332)
NetR1_1: R1.1 U1.1 | length 2.4
  Top Layer w0.508: U1.1@90.361,19.431 92.202,19.431 92.545,19.774 R1.1@92.583,19.774
NetR2_1: R2.1 R4.2 | length 2.2
  Top Layer w0.508: R4.2@63.68,35.56 R2.1@65.86,35.56
NetR3_1: R3.1 R5.2 | length 2.2
  Top Layer w0.508: R3.1@73.84,35.56 R5.2@76.02,35.56
NetR13_2: R13.2 R21.2 T1.8 | length 32
  Top Layer w0.508: R21.2@56.374,54.969 56.374,54.878 56.388,54.864 56.768,55.244 v2(58.42,55.244) R13.2@60.165,55.244
  Mid-Layer 2 w0.508: v2(58.42,55.244) 65.66,55.244 67.12,53.785 72.707,53.785 73.406,53.086 73.406,44.323 71.12,42.037 71.097,42.06 T1.8@71.06,42.06
NetR15_1: R15.1 R19.2 | length 2.6
  Top Layer w0.508: R15.1@56.515,31.49 R19.2@56.515,34.11
NetR29_1: R29.1 R31.1 U4.1 | length 6.2
  Top Layer w0.508: U4.1@90.562,33.742 91.353,33.742 91.44,33.655 91.859,33.655 R31.1@92.71,34.506 92.799,34.417 93.726,34.417 93.853,34.544 93.853,35.687 94.234,36.068 94.869,36.068 94.958,36.157 R29.1@94.958,36.195
NetR49_1: R49.1 U7.27 | length 15
  Top Layer w0.254: U7.27@119.697,29.03 119.699,29.032 120.373,29.032 120.552,29.21 v1(120.675,29.21) ; v9(130.124,31.725) 130.15,31.75 R49.1@131.153,31.75
  Bottom Layer w0.254: v1(120.675,29.21) 120.675,29.134 121.361,29.134 121.361,28.992 121.778,28.575 122.657,28.575 123.038,28.194 129.007,28.194 129.946,29.134 129.946,31.547 v9(130.124,31.725)
NetR50_2: R50.2 U7.19 | length 12.4
  Top Layer w0.254: U7.19@119.697,25.03 119.801,25.03 119.812,25.019 120.111,25.019 120.264,24.867 120.599,24.867 120.726,24.74 v1@120.929,24.74 ; v1(130.048,22.555) 131.102,22.555 R50.2@131.153,22.606
  Bottom Layer w0.254: v1(120.955,24.663) 123.012,22.606 v1@130.048,22.606
NetR51_2: R51.2 U7.25 | length 14.5
  Top Layer w0.254: U7.25@119.697,28.03 119.699,28.028 120.17,28.028 120.202,27.995 120.803,27.995 120.814,27.983 121.469,27.983 v1(121.551,27.901) ; R51.2@131.153,29.972 131.953,29.172 v1(131.953,28.88)
  Bottom Layer w0.254: v1(121.551,27.901) 121.602,27.901 121.641,27.94 121.793,27.788 122.762,27.788 122.838,27.711 129.206,27.711 130.629,29.134 131.699,29.134 v1(131.953,28.88)
NetR52_2: R52.2 U7.21 | length 12.2
  Top Layer w0.254: U7.21@119.697,26.03 119.741,26.03 119.758,26.012 120.483,26.012 120.638,25.857 121.996,25.857 v1(122.022,25.832) ; v1(129.972,24.435) 131.102,24.435 R52.2@131.153,24.384
  Bottom Layer w0.254: v1(122.022,25.832) 122.022,25.806 122.809,25.019 129.388,25.019 v1(129.972,24.435)
NetR56_1: R56.1 R58.2 R102.1 U7.34 | length 10.7
  Top Layer w0.254: U7.34@116.547,30.18 116.549,30.182 116.549,30.824 116.599,30.875 116.599,32.935 116.793,33.129 118.473,33.129 118.669,33.325 118.669,35.56 ; R58.2@117.729,35.598 117.767,35.56 118.669,35.56 ; R56.1@119.634,35.598 119.634,35.56 118.669,35.56
  Top Layer w0.3: R56.1@119.634,35.598 R102.1@121.158,35.598
NetR58_1: R58.1 R61.2 U7.35 | length 6
  Top Layer w0.254: U7.35@116.047,30.18 116.047,31.005 116.117,31.074 116.117,31.813 115.799,32.131 115.799,32.995 115.824,33.02 R61.2@115.824,33.998 116.624,33.998 116.713,33.909 117.64,33.909 R58.1@117.729,33.998
NetR59_2: R59.2 R60.1 U7.12 | length 7.2
  Top Layer w0.254: U7.12@116.047,24.38 116.047,23.972 115.316,23.241 115.316,22.009 115.735,21.59 R60.1@115.735,21.031 115.735,20.13 116.713,19.152 117.757,19.152 R59.2@117.803,19.105
NetR60_2: R60.2 U7.11 | length 3.9
  Top Layer w0.254: R60.2@114.135,21.031 114.135,22.967 U7.11@115.547,24.38
NetR62_2: R62.2 U7.5 | length 26.5
  Top Layer w0.254: v1(111.735,28.677) 111.735,28.562 112.065,28.232 112.065,28.153 112.481,27.737 112.674,27.737 112.751,27.661 112.893,27.661 113.024,27.53 U7.5@114.897,27.53 ; R62.2@113.274,8.775 R62.2@113.286,8.763
  Top Layer w0.4: R62.2@113.286,8.763 v9(114.3,8.763)
  Mid-Layer 2 w0.254: v1(111.735,28.677) 111.681,28.623 111.681,27.94 111.404,27.664 111.404,25.806 110.871,25.273 110.871,14.732 114.3,11.303 v9(114.3,8.763)
NetR63_2: R63.2 U7.4 | length 28.8
  Top Layer w0.254: v1(112.776,28.448) 113.068,28.156 113.322,28.156 113.466,28.012 114.753,28.012 114.771,28.03 U7.4@114.897,28.03 ; R63.2@118.098,8.775 118.11,8.763 v1(119.126,8.763)
  Mid-Layer 2 w0.254: v1(112.776,28.448) 112.776,28.321 111.887,27.432 111.887,25.607 111.354,25.073 111.354,15.773 115.062,12.065 115.062,9.398 115.697,8.763 v1(119.126,8.763)
NetR64_2: R64.2 U7.6 | length 29
  Top Layer w0.254: v1@112.522,26.797 112.598,26.873 v1(112.598,26.949) 112.68,27.032 114.91,27.032 114.91,27.026 114.906,27.03 U7.6@114.897,27.03 ; R64.2@122.907,8.775 122.936,8.804 v1(122.936,10.033)
  Mid-Layer 2 w0.254: v1(112.598,26.949) 112.598,25.959 114.935,23.622 114.935,13.208 115.697,12.446 115.697,10.541 116.205,10.033 v1(122.936,10.033)
NetR65_2: R65.2 U7.36 | length 6.7
  Top Layer w0.254: R65.2@110.401,30.48 v1(111.633,30.48) ; v1(115.406,31.369) 115.406,31.245 115.547,31.104 U7.36@115.547,30.18
  Bottom Layer w0.254: v1(111.633,30.48) 111.887,30.734 114.808,30.734 115.443,31.369 v1(115.406,31.369)
NetR66_2: R66.2 U7.9 | length 5.3
  Top Layer w0.254: R66.2@110.401,23.495 111.684,23.495 113.718,25.53 U7.9@114.897,25.53
NetR67_2: R67.2 U7.10 | length 5.8
  Top Layer w0.254: R67.2@110.401,21.844 110.439,21.844 111.608,23.012 111.884,23.012 113.901,25.03 U7.10@114.897,25.03
NetR70_1: R70.1 R72.2 | length 3.6
  Top Layer w0.508: R72.2@53.287,16.002 R70.1@53.287,19.558
NetR73_1: R73.1 U8.6 | length 4.1
  Top Layer w0.508: U8.6@91.048,13.716 92.71,13.716 93.472,12.954 94.488,12.954 94.525,12.991 R73.1@94.791,12.991
NetR74_1: R74.1 U8.7 | length 3.9
  Top Layer w0.508: U8.7@91.048,14.986 92.964,14.986 93.218,14.732 94.735,14.732 R74.1@94.791,14.676
NetR77_1: R77.1 R78.2 U11.3 | length 3.9
  Top Layer w0.508: R77.1@107.546,14.328 R78.2@107.546,16.136 107.629,16.053 U11.3@109.581,16.053
NetR90_2: R90.2 U2.5 | length 6.7
  Top Layer w0.508: U2.5@116.89,60.867 117.09,60.867 117.136,60.913 117.136,61.686 117.933,62.484 118.999,62.484 120.396,62.484 120.904,62.992 120.904,64.205 120.961,64.262 R90.2@120.999,64.224
NetT1_3: T1.3 T1.4 | length 5.5
  Top Layer w0.508: T1.4@71.06,62.06 71.06,61.909 T1.4@71.12,61.849
  Top Layer w1.524: T1.3@71.06,67.06 71.12,67 T1.4@71.12,61.849
NetT2_1: T2.1 U12.3 | length 3.6
  Top Layer w0.508: T2.1@91.253,3.427 91.633,3.427 92.71,4.504 92.71,4.699 93.218,5.207 93.9,5.207 U12.3@93.99,5.297
NetT2_3: T2.3 U12.1 | length 4.8
  Top Layer w0.508: T2.3@91.255,10.022 92.572,10.022 92.583,10.033 93.091,9.525 93.091,8.382 93.948,7.525 93.948,7.239 U12.1@93.99,7.197
PFC_off: J4.37 R1.2 | length 162
  Top Layer w0.508: R1.2@92.583,21.374 92.672,21.374 92.71,21.336 v2(92.71,22.606)
  Mid-Layer 2 w0.508: v2(92.71,22.606) 90.805,20.701 90.805,6.223 91.288,5.74 92.28,5.74 92.763,5.258 157.123,5.258 157.961,6.096 173.736,6.096 176.911,9.271 176.911,52.451 171.758,57.604 169.729,57.604 169.656,57.531 168.91,57.531 167.64,58.801 167.71,58.871 J4.37@167.71,58.887
PFC_off1: C6.1 D1.2 D100.1 Q1.3 Q2.1 Q3.3 R5.1 | length 38.6
  Top Layer w0.508: 69.342,24.384 v2(67.945,25.781) 67.945,27.409 Q2.1@67.916,27.438 68.416,27.438 70.101,29.123 70.101,29.164 D100.1@70.147,29.21 70.17,29.233 70.17,30.838 C6.1@70.193,30.861 ; v2(74.676,25.527) 74.608,25.459 74.608,25.078 74.422,24.892 74.422,24.43 74.376,24.384 Q1.3@74.365,24.384 74.365,23.076 75.889,21.552 75.914,21.577 D1.2@75.95,21.577 ; v2(78.867,33.02) 78.893,33.046 78.893,35.534 R5.1@78.92,35.56
  Mid-Layer 2 w0.508: v2(67.945,25.781) 74.326,25.781 74.58,25.527 v2(74.676,25.527)
  Bottom Layer w0.508: v2(67.945,25.781) 69.342,27.178 76.708,27.178 78.867,29.337 v2(78.867,33.02)
PFC_off2: D2.2 D13.1 D14.1 Q4.1 R14.1 | length 37.4
  Top Layer w0.508: R14.1@59.52,45.878 60.21,45.878 Q4.1@61.11,44.978 61.235,44.853 D13.1@61.235,43.308 61.214,43.287 D14.1@61.214,41.402 ; v2(61.214,39.878) D14.1@61.214,41.402 ; D14.1@61.235,41.271 61.235,41.381 D14.1@61.214,41.402 ; v11(75.184,20.447) 75.85,19.781 D2.2@75.85,19.54
  Mid-Layer 2 w0.508: v2(61.214,39.878) 61.214,34.798 62.738,33.274 62.738,27.94 71.247,19.431 74.168,19.431 v11(75.184,20.447)
PGND: C2.2 C3.2 D3.4 H1.1 H1.2 H2.1 H2.2 NT2.2 R27.1 R28.1
  other v3: 48.006,59.436 48.006,61.214 48.006,62.738 48.006,64.262 48.006,65.786
REG_N: C50.2 R54.1 R69.2 U7.24 | length 28.3
  Top Layer w0.254: v1(108.638,25.132) 108.698,25.132 108.839,25.273 108.839,25.146 R69.2@108.801,25.146 ; U7.24@119.697,27.53 119.868,27.53 119.886,27.512 120.603,27.512 121.064,27.051 v1(121.15,27.051) ; R54.1@123.538,30.353 v1(124.612,30.353) 125.52,30.353 C50.2@125.575,30.408
  Bottom Layer w0.254: v1(108.638,25.132) 113.933,25.132 115.062,24.003 119.38,24.003 119.888,24.511 119.888,25.781 121.158,27.051 120.777,27.051 120.015,27.813 120.015,28.865 119.964,28.915 119.964,29.505 120.015,29.555 120.015,30.48 120.472,30.937 124.003,30.937 124.587,30.353 v1(124.612,30.353)
SCL: J3.9 J5.2 R80.1 U7.1 | length 89.4
  Top Layer w0.254: v1(114.808,32.385) 114.808,32.261 114.694,32.148 114.694,30.612 114.897,30.41 U7.1@114.897,29.53
  Top Layer w0.508: J3.9@124.53,71.587 123.19,72.927 123.19,76.454 123.834,77.098 R80.1@124.53,77.098
  Mid-Layer 2 w0.254: J5.2@102.87,9.613 104.355,8.128 105.791,8.128 106.68,9.017 106.68,14.097 110.363,17.78 110.363,25.146 110.185,25.324 110.119,25.324 109.703,25.74 109.703,29.083 109.728,29.108 109.728,30.48 110.744,31.496 112.141,31.496 112.903,30.734 113.97,30.734 114.694,31.459 114.694,31.664 114.721,31.69 v1@114.721,32.385 ; v1(114.808,32.385) 115.443,33.02 115.443,35.56 118.364,38.481 118.364,44.958 119.126,45.72 119.126,55.88 120.269,57.023 120.269,69.215 122.641,71.587 J3.9@124.53,71.587
SDA: J3.10 J5.3 R81.1 U7.2 | length 86.3
  Top Layer w0.254: v1(113.284,31.496) 113.284,31.42 114.046,30.658 114.046,29.362 114.379,29.03 U7.2@114.897,29.03
  Top Layer w0.508: J3.10@124.53,74.127 124.501,74.127 124.46,74.168 124.46,75.184 126.289,77.013 R81.1@126.289,77.098
  Mid-Layer 2 w0.254: J5.3@105.41,9.613 105.41,10.541 106.197,11.328 106.197,14.297 109.88,17.98 109.88,24.88 109.22,25.541 109.22,32.004 110.49,33.274 112.522,33.274 ; v1(113.284,31.496) 112.522,32.258 112.522,33.274 ; J3.10@124.53,74.127 124.362,74.295 121.412,74.295 119.761,72.644 119.761,57.277 118.618,56.134 118.618,46.101 117.856,45.339 117.856,38.735 114.681,35.56 113.411,35.56 112.522,34.671 112.522,33.274
SGND: C1.1 C7.2 C8.2 C9.2 C10.2 C14.2 C15.2 C16.2 C19.2 C29.2 C30.2 C31.2 C32.2 C33.2 C36.2 C37.2 C38.2 C39.2 C40.2 C41.2 C42.2 C43.2 C44.2 C47.2 C50.1 C52.1 C56.1 C57.1 C58.2 C62.2 C63.1 C64.1 C65.1 C66.1 C68.1 C69.1 C70.2 C72.2 C73.2 C74.2 C75.2 C101.1 D15.2 D30.2 D31.1 D102.2 J1.1 J2.3 J3.22 J4.20 J5.1 NT1.1 Q5.3 Q17.1 Q17.2 Q17.3 Q18.1 Q18.2 Q18.3 R37.1 R76.1 R78.1 R86.2 R87.2 R94.1 U1.2 U2.2 U5.3 U7.17 U7.22 U7.37 U8.5 U9.2 U11.2 U12.4 U12.5 U13.1 | length 18.3
  Top Layer w0.4: C16.2@118.453,61.087 C16.2@118.618,61.087
  Top Layer w0.508: U11.2@109.581,17.003 109.489,17.003 109.474,17.018 110.49,17.018 110.744,16.764 110.744,15.24 109.865,14.361 C62.2@109.865,14.055 ; C15.2@112.268,60.49 112.306,60.452 113.067,60.452 113.367,60.152 113.555,59.963 114.094,59.963 U2.2@114.14,59.917 ; U2.2@113.819,59.917 U2.2@114.14,59.917 ; 115.182,59.944 115.156,59.917 ; C16.2@118.453,61.087 118.453,61.011 117.36,59.917 115.156,59.917 ; C16.2@118.618,61.011 118.635,61.027 120.633,61.027 D102.2@120.65,61.044 ; U2.2@114.14,59.917 115.156,59.917
  Top Layer w1: 115.156,59.975 115.57,60.39 Q5.3@115.57,64.028
  other v1: 93.345,3.175 91.44,4.826 97.79,7.112 91.821,8.128 98.679,8.255 98.171,9.906 98.298,11.176 121.666,11.43 122.555,11.43 91.821,11.684 118.872,13.335 98.552,14.859 150.368,15.748 152.654,15.748 98.552,15.875 149.225,16.129 151.511,16.129 116.459,16.256 149.225,17.018 151.511,17.018 163.957,18.161 163.957,19.431 163.957,20.574 163.957,21.717 163.957,22.86 103.759,23.114 163.957,24.003 163.957,25.146 146.939,25.273 98.679,25.781 146.939,26.289 148.59,26.289 163.957,26.416 98.679,26.67 95.504,27.813 97.536,27.813
  other v2: 155.702,8.255 165.989,8.763 155.702,9.398 166.624,9.779 155.702,10.541 166.116,10.795 167.259,10.795
  other v3: 106.045,38.735 107.95,38.735 106.045,41.275 107.95,41.275 106.045,43.815 107.95,43.815 106.045,46.355 107.95,46.355 106.045,48.895 107.95,48.895 106.045,51.435 107.95,51.435 106.045,53.975 107.95,53.975 106.045,56.515 107.95,56.515
  other v4: 137.135,37.211 138.151,37.211 139.294,37.211 134.595,38.1 135.611,38.1 136.627,38.1 137.643,38.1 138.659,38.1 139.802,38.1 125.857,41.783 126.873,41.783 127.889,41.783 129.413,41.783 130.429,41.783 131.318,41.783 133.223,41.783 134.239,41.783 135.255,41.783 137.033,41.783 138.049,41.783 139.065,41.783 132.08,44.323 133.096,44.323 134.112,44.323 135.128,44.323 136.144,44.323 137.16,44.323 138.176,44.323 139.192,44.323 140.208,44.323 120.142,77.089 121.285,77.089 120.142,78.105 121.285,78.105
  other v5: 133.223,13.589 134.493,13.589 135.763,13.589 137.033,13.589 131.953,14.732 133.223,14.732 134.493,14.732 135.763,14.732 137.033,14.732 138.176,17.78 139.446,17.78 140.716,17.78 141.986,17.78 112.776,63.5 114.046,63.5 117.094,63.5 118.364,63.5 112.776,64.77 114.046,64.77 117.094,64.77 118.364,64.77 112.776,66.04 114.046,66.04 117.094,66.04 118.364,66.04
  other v8: 116.459,17.272 116.459,18.161 92.202,30.988 91.44,31.496 92.202,31.877 100.076,31.877 100.965,31.877 101.854,31.877 102.743,31.877 103.632,31.877
  other v9: 99.06,7.112 100.457,7.112 93.726,11.938 121.158,16.002 121.158,17.018 121.158,18.034 100.838,20.828 100.838,21.717 100.838,22.606 145.923,25.273 145.923,26.289 145.923,27.305
  other v10: 116.682,25.23 117.912,25.23 115.747,26.12 116.682,26.12 117.912,26.12 118.847,26.12 115.747,27.28 116.682,27.28 117.912,27.28 118.847,27.28 115.747,28.44 116.682,28.44 117.912,28.44 118.847,28.44 116.682,29.33 117.912,29.33
  other v14: 123.571,27.051
SYSTEM: C33.1 C36.1 C37.1 C38.1 C39.1 D26.2 J1.3 Q14.5 Q14.6 Q14.7 Q14.8 Q14.9@152.106,7.983 Q15.5 Q15.6 Q15.7 Q15.8 Q15.9 R46.2 R48.2 R84.2 U7.32 | length 75.3
  Top Layer w0.254: v1(105.385,15.682) 105.41,15.656 D26.2@105.41,14.932 ; U7.32@117.547,30.18 117.565,30.197 117.565,31.284 v1(117.816,31.536) ; v1(134.62,66.294) 135.022,65.892 R84.2@135.022,65.024
  Mid-Layer 2 w0.254: v1(134.62,66.294) 134.493,66.294 135.89,64.897 140.843,64.897 146.177,59.563 146.177,49.911 145.415,49.149 145.415,41.91 145.412,41.907 C33.1@145.412,41.87
  Bottom Layer w0.254: v1(105.385,15.682) 105.385,15.977 105.41,15.951 105.41,19.787 107.34,21.717 107.34,26.035 107.848,26.543 108.966,26.543 109.474,27.051 109.474,29.362 109.855,29.743 111.912,29.743 112.446,29.21 115.443,29.21 117.769,31.536 v1(117.816,31.536) 117.87,31.536 117.907,31.572 119.456,31.572 119.609,31.42 127.457,31.42 128.524,32.487 128.524,34.53 128.542,34.548
  other v2: 150.622,6.985 151.638,6.985 152.654,6.985 153.67,6.985 150.622,8.255 151.638,8.255 152.654,8.255 153.67,8.255 150.622,9.525 151.638,9.525 152.654,9.525 153.67,9.525
  other v5: 143.891,39.878 145.288,39.878 146.431,40.513 143.891,41.275 143.891,42.545
  other v7: 129.667,34.798 130.556,34.798 129.667,35.56 130.556,35.56 129.667,36.322 130.556,36.322
VAC-u: C51.2 R71.2 R79.1 U9.4 | length 26.9
  Top Layer w0.508: C51.2@96.383,10.965 96.266,10.848 96.266,9.144 97.536,9.144 v2(97.536,9.017) ; v2(101.346,19.431) 101.346,19.992 U9.4@102.219,20.865 ; R79.1@105.41,24.3 105.41,24.257 v2(106.426,24.257)
  Mid-Layer 2 w0.508: v2(97.536,9.017) 97.536,9.113 97.307,9.342 97.307,12.598 97.536,12.827 97.536,17.653 99.695,19.812 100.838,19.812 101.219,19.431 v2(101.346,19.431) 106.172,24.257 v2(106.426,24.257)
VDD: C11.1 C22.1 D11.3 D16.1 R18.2 R30.1 R35.1 U3.8 | length 62.9
  Top Layer w0.5: C11.1@37.33,47.824 37.33,47.76 37.465,47.625 40.132,47.625 ; v2(40.132,46.736) 40.132,47.625 ; R30.1@41.774,46.68 41.774,47.625 ; R35.1@49.479,46.68 49.53,46.731 49.53,47.752 48.514,48.768 45.72,48.768 43.623,50.865 C22.1@43.589,50.865 43.444,50.719 43.444,49.794 42.88,49.794 42.871,49.784 42.418,49.784 41.989,49.355 41.989,48.815 41.774,48.6 41.774,47.625 ; R18.2@56.426,42.926 56.388,42.888 v2(56.388,41.402) 57.785,41.402 60.706,38.481 v2(64.516,38.481) ; D11.3@75.268,32.258 75.29,32.28 75.29,32.999 v2(75.311,33.02) ; 40.132,47.625 41.774,47.625
  Mid-Layer 2 w0.5: v2(40.132,46.736) 45.466,41.402 v2(56.388,41.402) ; v2(64.516,38.481) 65.536,37.461 65.536,36.699 69.215,33.02 v2(75.311,33.02)
pads on no net: J1.2 J3.2 J3.3 J3.4 J3.6 J3.7 J3.21 J3.24 J3.27 J3.28 J3.29 J3.30 J4.11 J4.12 J4.13 J4.14 J4.15 J4.16 J4.17 J4.18 J4.19 J4.31 J4.32 J4.33 J4.34 J4.35 J4.36 J4.38 J5.4 Q11.9@119.2,53.595 Q11.9@119.2,55.375 Q11.9@120.65,53.595 Q11.9@120.65,54.525 Q11.9@120.65,55.375 Q11.9@122.1,53.595 Q11.9@122.1,55.375 Q12.9@119.2,43.05 Q12.9@119.2,44.83 Q12.9@120.65,43.05 Q12.9@120.65,43.9 Q12.9@120.65,44.83 Q12.9@122.1,43.05 Q12.9@122.1,44.83 Q13.9@141.348,6.525 Q13.9@141.348,7.975 Q13.9@141.348,9.425 Q13.9@142.198,7.975 Q13.9@143.128,6.525 Q13.9@143.128,7.975 Q13.9@143.128,9.425 Q14.9@150.721,6.533 Q14.9@150.721,7.983 Q14.9@150.721,9.433 Q14.9@151.651,7.983 Q14.9@152.501,6.533 Q14.9@152.501,7.983 Q14.9@152.501,9.433 T1.1 T1.6 T1.12 T1.16 U10.4 U10.5 U13.4 U13.5

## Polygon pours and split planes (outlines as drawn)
NetD103_1 on Bottom Layer "BOTTOM_LAYER_NETD103_1_P068" (solid, remove dead copper, pour order 68): 46.863,83.947 48.133,82.677 59.563,82.677 60.452,83.566 60.452,88.011 58.928,89.535 48.133,89.535 46.863,88.265
NetD5_1 on Bottom Layer "BOTTOM_LAYER_NETD5_1_P133" (solid, remove dead copper, pour order 133): 41.106,80.01 51.435,80.01 52.324,79.121 52.324,73.279 51.435,72.39 45.466,72.39 44.069,70.993 41.275,70.993 40.259,72.009 40.259,79.375
NetD4_1 on Bottom Layer "BOTTOM_LAYER_NETD4_1_P095" (solid, remove dead copper, pour order 95): 44.831,82.931 45.847,83.947 45.847,88.392 44.831,89.408 25.654,89.408 24.892,88.646 24.892,83.82 25.781,82.931
SYSTEM on Bottom Layer "BOTTOM_LAYER_SYSTEM_P129" (solid, pour order 129): 144.145,44.45 149.86,44.45 152.4,41.91 163.83,41.91 167.005,38.735 167.005,35.56 168.91,33.655 172.085,33.655 173.355,32.385 173.355,24.765 172.72,24.13 172.72,22.86 155.575,5.715 151.13,5.715 142.875,13.97 142.875,15.24 142.875,43.18
NetC45_1 on Bottom Layer "BOTTOM_LAYER_NETC45_1_P096" (solid, pour order 96): 132.588,19.431 135.382,19.431 135.382,16.637 132.588,16.637
NetC40_1 on Bottom Layer "BOTTOM_LAYER_NETC40_1_P093" (solid, pour order 93): 127.508,18.669 130.302,18.669 130.302,15.875 127.508,15.875
NetC46_1 on Bottom Layer "BOTTOM_LAYER_NETC46_1_P090" (solid, pour order 90): 133.731,36.322 136.525,36.322 136.525,33.528 133.731,33.528
SYSTEM on Bottom Layer "BOTTOM_LAYER_SYSTEM_P086" (solid, pour order 86): 128.397,36.957 131.191,36.957 131.191,34.163 128.397,34.163
SGND on Bottom Layer "BOTTOM_LAYER_SGND_P104" (solid, pour order 104): 118.745,66.802 119.507,67.564 119.507,78.486 119.888,78.867 121.666,78.867 121.793,78.74 121.793,66.294 118.618,63.119 116.586,63.119 116.459,63.246 116.459,66.802
+24V on Bottom Layer "BOTTOM_LAYER_+24V_P102" (solid, pour order 102): 97.155,57.785 132.08,57.785 133.985,59.69 137.795,59.69 139.065,58.42 139.065,52.705 122.555,36.195 103.505,36.195 97.155,42.545
NetQ5_4 on Bottom Layer "BOTTOM_LAYER_NETQ5_4_P100" (solid, pour order 100): 97.155,83.82 114.3,83.82 115.57,82.55 115.57,80.645 116.84,79.375 118.11,79.375 118.745,78.74 118.745,67.945 118.11,67.31 108.585,67.31 107.315,66.04 107.315,60.325 106.68,59.69 98.425,59.69 97.155,60.96
PGND on Bottom Layer "BOTTOM_LAYER_PGND_P098" (solid, pour order 98): 58.674,24.765 81.026,47.117 81.026,83.82 27.305,83.82 27.305,82.169 24.13,78.994 7.239,78.994 7.239,39.751 22.225,24.765 55.88,24.765
NetC4_1 on Bottom Layer "BOTTOM_LAYER_NETC4_1_P081" (solid, pour order 81): 59.828,5.08 60.96,6.212 60.96,11.607 60.93,11.607 59.69,12.847 45.943,12.847 38.25,20.54 32.862,20.54 31.962,19.64 31.962,17.103 33.055,16.01 36.183,16.01 39.91,12.283 47.113,5.08
CGND on Top Layer "TOP_LAYER_CGND_P139" (solid, remove dead copper, pour order 139): 81.534,38.989 81.534,84.455 78.994,86.995 75.184,86.995 66.167,77.978 66.167,44.958
NetQ2_2 on Top Layer "TOP_LAYER_NETQ2_2_P137" (solid, remove dead copper, pour order 137): 60.071,36.449 60.071,35.052 58.039,33.02 58.039,26.67 58.166,26.543 64.008,26.543 64.262,26.797 64.262,32.893 63.5,33.655 62.357,33.655 61.468,34.544 61.468,36.449
BAT on Top Layer "TOP_LAYER_BAT_P069" (solid, remove dead copper, pour order 69): 153.162,14.605 153.162,24.13 153.797,24.765 155.956,24.765 156.464,24.257 156.464,21.844 160.782,17.526 160.782,14.605
NetD6_1 on Top Layer "TOP_LAYER_NETD6_1_P136" (solid, remove dead copper, pour order 136): 53.467,79.121 53.467,71.755 54.864,70.358 61.595,70.358 63.5,72.263 63.5,77.978 62.357,79.121 61.214,79.121 60.198,80.137 54.483,80.137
